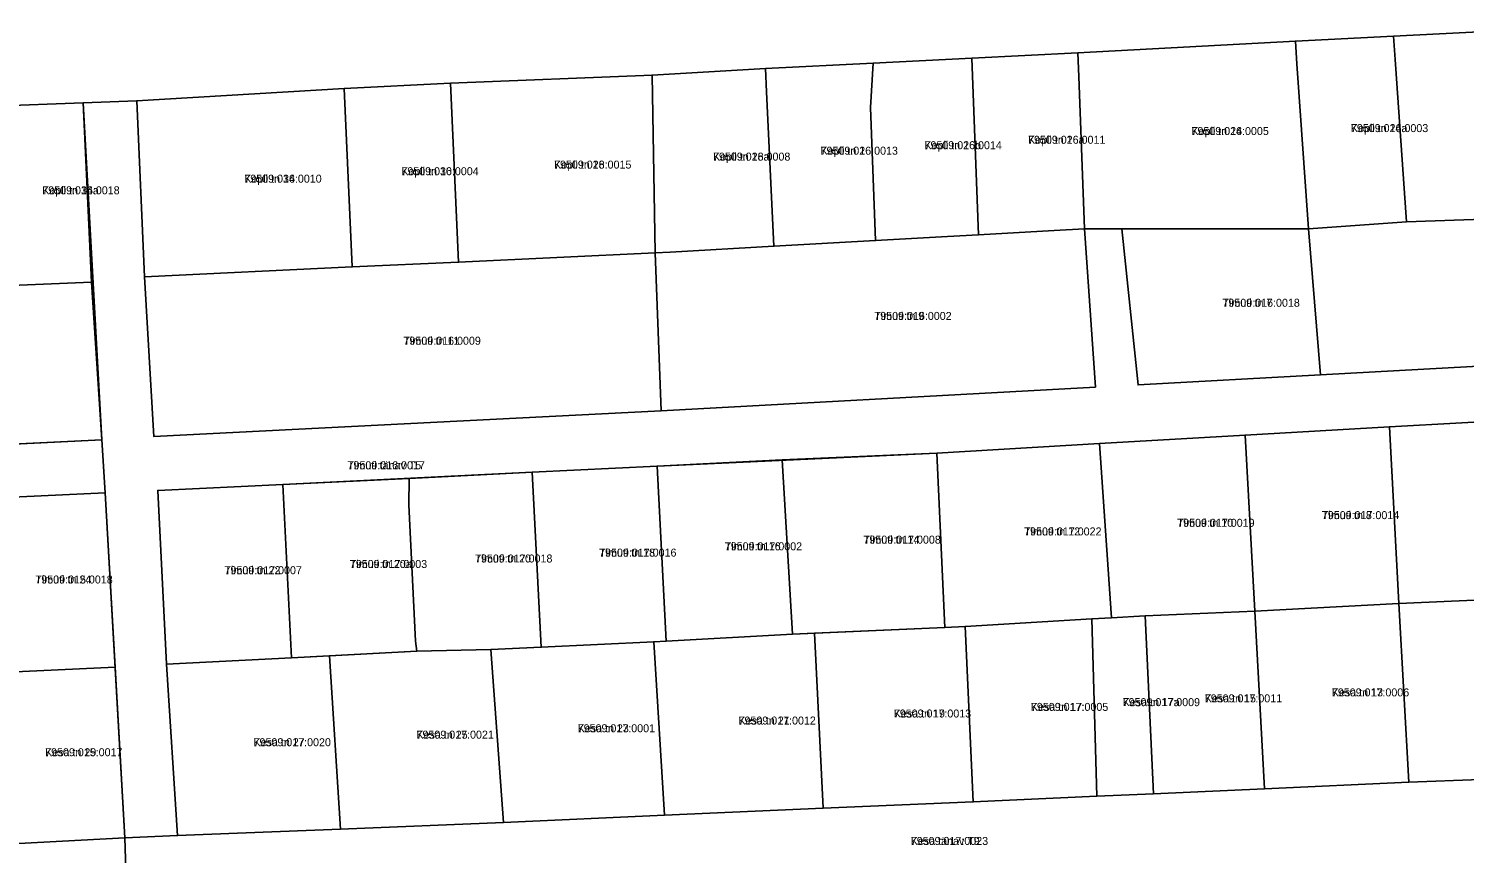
# Model space of a CAD drawing. Extents: x 643847 to 663718, y 6468443 to 6482775.
# Drawn here: x 658298.3 to 658567.5, y 6470602 to 6470756.7 of the extents above; entities that cross this region are included whole.
import ezdxf

# ---------------------------------------------------------------- set-up
doc = ezdxf.new("R2010")
doc.units = 0
for name, color, linetype in [('L_AADRESS', 7, 'Continuous'), ('PIIR', 7, 'Continuous'), ('TUNNUS', 7, 'Continuous')]:
    doc.layers.add(name, color=color, linetype=linetype)

msp = doc.modelspace()

# ---------------------------------------------------------------- linework, layer by layer
at = {"layer": 'PIIR'}
for points in [[(658581.35, 6470756.68), (658554.21, 6470755.25), (658535.81, 6470754.34), (658495.04, 6470752.13), (658475.12, 6470751.12), (658456.62, 6470750.22), (658436.48, 6470749.23), (658415.19, 6470747.98), (658377.43, 6470746.46), (658357.46, 6470745.45), (658318.59, 6470743.16), (658308.52, 6470742.77), (658291.63, 6470742.12)], [(658580.55, 6470683.5), (658553.44, 6470682.01), (658526.37, 6470680.43), (658499.11, 6470678.85), (658468.58, 6470677.06), (658416.13, 6470674.63), (658392.73, 6470673.47), (658345.97, 6470671.18), (658322.51, 6470670.05), (658324.14, 6470637.47), (658326.25, 6470605.28), (658316.37, 6470604.88), (658312.66, 6470669.61), (658312.03, 6470679.56), (658308.52, 6470742.77), (658318.59, 6470743.16), (658320.01, 6470710.13), (658321.76, 6470680.18), (658416.9, 6470684.97), (658492.61, 6470689.12), (658498.33, 6470689.43), (658496.26, 6470719.12), (658503.26, 6470719.11), (658506.32, 6470689.85), (658540.53, 6470691.75), (658606.65, 6470695.38)], [(658221.77, 6470675.13), (658312.03, 6470679.56), (658312.66, 6470669.61), (658284.6, 6470668.28)], [(658316.86, 6470589.09), (658316.37, 6470604.88), (658326.25, 6470605.28), (658356.81, 6470606.51), (658387.35, 6470607.75), (658417.53, 6470609.14), (658447.27, 6470610.41), (658475.4, 6470611.62), (658498.57, 6470612.66), (658509.23, 6470613.15), (658530.03, 6470614.09), (658557.08, 6470615.29), (658583.98, 6470616.29)], [(658244.43, 6470601.22), (658266.31, 6470602.21), (658288.22, 6470603.38), (658316.37, 6470604.88), (658316.86, 6470589.09)]]:
    msp.add_lwpolyline(points, dxfattribs=at)
for points in [[(658554.21, 6470755.25), (658554.5, 6470750.91), (658556.63, 6470720.42), (658538.28, 6470719.16), (658536.11, 6470750.06), (658535.81, 6470754.34)], [(658581.35, 6470756.68), (658583.5, 6470721.39), (658556.63, 6470720.42), (658554.5, 6470750.91), (658554.21, 6470755.25)], [(658535.81, 6470754.34), (658536.11, 6470750.06), (658538.28, 6470719.16), (658496.26, 6470719.12), (658495.21, 6470747.73), (658495.04, 6470752.13)], [(658436.48, 6470749.23), (658456.62, 6470750.22), (658456.14, 6470741.89), (658457.11, 6470716.93), (658438.05, 6470715.85), (658436.68, 6470744.84)], [(658456.62, 6470750.22), (658475.12, 6470751.12), (658476.4, 6470718.02), (658470.57, 6470717.69), (658457.11, 6470716.93), (658456.14, 6470741.89)], [(658495.04, 6470752.13), (658495.21, 6470747.73), (658496.26, 6470719.12), (658490.57, 6470718.8), (658476.4, 6470718.02), (658475.12, 6470751.12)], [(658377.43, 6470746.46), (658415.19, 6470747.98), (658415.79, 6470714.6), (658378.92, 6470712.87)], [(658436.48, 6470749.24), (658436.68, 6470744.84), (658438.05, 6470715.85), (658418.56, 6470714.75), (658415.79, 6470714.6), (658415.19, 6470747.98)], [(658357.46, 6470745.45), (658358.97, 6470711.98), (658320.01, 6470710.13), (658318.59, 6470743.16)], [(658377.43, 6470746.46), (658378.92, 6470712.87), (658358.97, 6470711.98), (658357.46, 6470745.45)], [(658308.52, 6470742.77), (658310.11, 6470709.13), (658293.58, 6470708.44), (658292.07, 6470737.05), (658291.63, 6470742.12)], [(658540.53, 6470691.75), (658538.28, 6470719.16), (658556.63, 6470720.42), (658583.5, 6470721.39), (658605.49, 6470722.19), (658606.65, 6470695.38)], [(658492.61, 6470689.12), (658416.9, 6470684.97), (658415.79, 6470714.6), (658418.56, 6470714.75), (658438.05, 6470715.85), (658457.11, 6470716.93), (658470.57, 6470717.69), (658476.4, 6470718.02), (658490.57, 6470718.8), (658496.26, 6470719.12), (658498.33, 6470689.43)], [(658540.53, 6470691.75), (658506.32, 6470689.85), (658503.26, 6470719.11), (658538.28, 6470719.16)], [(658321.76, 6470680.18), (658320.01, 6470710.13), (658358.97, 6470711.98), (658378.92, 6470712.87), (658415.79, 6470714.6), (658416.9, 6470684.97)], [(658221.78, 6470675.18), (658220.3, 6470705.43), (658228.48, 6470705.55), (658260.82, 6470707.18), (658293.58, 6470708.44), (658310.11, 6470709.13), (658312.03, 6470679.56)], [(658580.55, 6470683.5), (658582.06, 6470650.04), (658555.19, 6470648.86), (658553.44, 6470682.01)], [(658526.37, 6470680.43), (658528.22, 6470647.38), (658507.63, 6470646.52), (658501.34, 6470646.17), (658499.11, 6470678.85)], [(658553.44, 6470682.01), (658555.19, 6470648.86), (658528.22, 6470647.38), (658526.37, 6470680.43)], [(658468.58, 6470677.06), (658470.07, 6470644.35), (658441.53, 6470643.09), (658439.59, 6470675.79)], [(658468.58, 6470677.06), (658499.11, 6470678.85), (658501.34, 6470646.17), (658497.63, 6470645.96), (658473.88, 6470644.54), (658470.07, 6470644.35)], [(658392.73, 6470673.47), (658416.13, 6470674.63), (658417.81, 6470641.78), (658415.52, 6470641.67), (658394.41, 6470640.62)], [(658439.59, 6470675.79), (658441.53, 6470643.09), (658417.81, 6470641.78), (658416.13, 6470674.63)], [(658369.61, 6470667.34), (658370.87, 6470641.77), (658371.09, 6470639.88), (658347.57, 6470638.62), (658345.97, 6470671.18), (658369.68, 6470672.32)], [(658392.73, 6470673.47), (658394.41, 6470640.62), (658384.97, 6470640.19), (658371.09, 6470639.88), (658370.87, 6470641.77), (658369.61, 6470667.34), (658369.68, 6470672.32)], [(658314.53, 6470636.89), (658286.43, 6470635.59), (658284.6, 6470668.28), (658312.66, 6470669.61)], [(658345.97, 6470671.18), (658347.57, 6470638.62), (658324.14, 6470637.47), (658322.51, 6470670.05)], [(658582.06, 6470650.04), (658583.98, 6470616.29), (658557.08, 6470615.29), (658555.19, 6470648.86)], [(658509.23, 6470613.15), (658507.63, 6470646.52), (658528.22, 6470647.38), (658530.03, 6470614.09)], [(658530.03, 6470614.09), (658528.22, 6470647.38), (658555.19, 6470648.86), (658557.08, 6470615.29)], [(658447.27, 6470610.41), (658445.63, 6470643.27), (658470.07, 6470644.35), (658473.88, 6470644.54), (658475.4, 6470611.62)], [(658475.4, 6470611.62), (658473.88, 6470644.54), (658497.63, 6470645.96), (658498.57, 6470612.66)], [(658498.57, 6470612.66), (658497.63, 6470645.96), (658501.34, 6470646.17), (658507.63, 6470646.52), (658509.23, 6470613.15)], [(658417.53, 6470609.14), (658415.52, 6470641.67), (658417.81, 6470641.78), (658441.53, 6470643.09), (658445.63, 6470643.27), (658447.27, 6470610.41)], [(658356.81, 6470606.51), (658354.7, 6470639), (658371.09, 6470639.88), (658384.97, 6470640.19), (658387.35, 6470607.75)], [(658387.35, 6470607.75), (658384.97, 6470640.19), (658394.41, 6470640.62), (658415.52, 6470641.67), (658417.53, 6470609.14)], [(658288.22, 6470603.38), (658286.43, 6470635.59), (658314.53, 6470636.89), (658316.37, 6470604.88)], [(658326.25, 6470605.28), (658324.14, 6470637.47), (658347.57, 6470638.62), (658354.7, 6470639), (658356.81, 6470606.51)]]:
    msp.add_lwpolyline(points, close=True, dxfattribs=at)

# ---------------------------------------------------------------- texts
at = {"layer": 'L_AADRESS'}
for s, p in [('Kopli tn 24a', (658546.22, 6470737.28)), ('Kopli tn 26a', (658485.69, 6470735.09)), ('Kopli tn 24', (658516.33, 6470736.73)), ('Kopli tn 28a', (658426.62, 6470731.93)), ('Kopli tn 26', (658446.79, 6470733.04)), ('Kopli tn 26b', (658466.27, 6470734.07)), ('Kopli tn 30', (658368.19, 6470729.19)), ('Kopli tn 28', (658396.82, 6470730.43)), ('Kopli tn 34', (658338.75, 6470727.79)), ('Kopli tn 36a', (658300.87, 6470725.61)), ('Timuti tn 7', (658522.14, 6470704.51)), ('Timuti tn 9', (658456.86, 6470702.04)), ('Timuti tn 11', (658368.59, 6470697.39)), ('Timuti tänav T5', (658358.1, 6470674.02)), ('Timuti tn 8', (658540.78, 6470664.67)), ('Timuti tn 10', (658513.66, 6470663.23)), ('Timuti tn 14', (658454.83, 6470660.07)), ('Timuti tn 12', (658484.96, 6470661.61)), ('Timuti tn 20', (658382.01, 6470656.53)), ('Timuti tn 18', (658405.27, 6470657.63)), ('Timuti tn 16', (658428.83, 6470658.82)), ('Timuti tn 22', (658335.04, 6470654.33)), ('Timuti tn 20a', (658358.53, 6470655.5)), ('Timuti tn 24', (658299.57, 6470652.59)), ('Kesa tn 17a', (658503.43, 6470629.58)), ('Kesa tn 15', (658518.83, 6470630.29)), ('Kesa tn 13', (658542.65, 6470631.41)), ('Kesa tn 19', (658460.52, 6470627.45)), ('Kesa tn 17', (658486.23, 6470628.69)), ('Kesa tn 23', (658401.25, 6470624.68)), ('Kesa tn 21', (658431.4, 6470626.13)), ('Kesa tn 27', (658340.48, 6470622.06)), ('Kesa tn 25', (658371.03, 6470623.48)), ('Kesa tn 29', (658301.4, 6470620.18)), ('Kesa tänav T9', (658463.7, 6470603.54))]:
    msp.add_text(s, height=1.5, dxfattribs=at).set_placement(p)
at = {"layer": 'TUNNUS'}
for s, p in [('79509:016:0003', (658546.22, 6470737.28)), ('79509:016:0011', (658485.69, 6470735.09)), ('79509:016:0005', (658516.33, 6470736.73)), ('79509:016:0008', (658426.62, 6470731.93)), ('79509:016:0013', (658446.79, 6470733.04)), ('79509:016:0014', (658466.27, 6470734.07)), ('79509:016:0004', (658368.19, 6470729.19)), ('79509:016:0015', (658396.82, 6470730.43)), ('79509:016:0010', (658338.75, 6470727.79)), ('79509:014:0018', (658300.87, 6470725.61)), ('79509:016:0018', (658522.14, 6470704.51)), ('79509:016:0002', (658456.86, 6470702.04)), ('79509:016:0009', (658368.59, 6470697.39)), ('79509:016:0017', (658358.1, 6470674.02)), ('79509:017:0014', (658540.78, 6470664.67)), ('79509:017:0019', (658513.66, 6470663.23)), ('79509:017:0008', (658454.83, 6470660.07)), ('79509:017:0022', (658484.96, 6470661.61)), ('79509:017:0018', (658382.01, 6470656.53)), ('79509:017:0016', (658405.27, 6470657.63)), ('79509:017:0002', (658428.83, 6470658.82)), ('79509:017:0007', (658335.04, 6470654.33)), ('79509:017:0003', (658358.53, 6470655.5)), ('79509:015:0018', (658299.57, 6470652.59)), ('79509:017:0009', (658503.43, 6470629.58)), ('79509:017:0011', (658518.83, 6470630.29)), ('79509:017:0006', (658542.65, 6470631.41)), ('79509:017:0013', (658460.52, 6470627.45)), ('79509:017:0005', (658486.23, 6470628.69)), ('79509:017:0001', (658401.25, 6470624.68)), ('79509:017:0012', (658431.4, 6470626.13)), ('79509:017:0020', (658340.48, 6470622.06)), ('79509:017:0021', (658371.03, 6470623.48)), ('79509:015:0017', (658301.4, 6470620.18)), ('79509:017:0023', (658463.7, 6470603.54))]:
    msp.add_text(s, height=1.5, dxfattribs=at).set_placement(p)

doc.saveas('drawing.dxf')
